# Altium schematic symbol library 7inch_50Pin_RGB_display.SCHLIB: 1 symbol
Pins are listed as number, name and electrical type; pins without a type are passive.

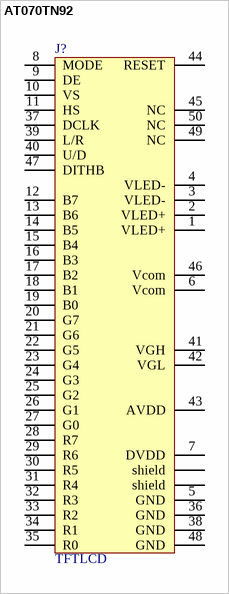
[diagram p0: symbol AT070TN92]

## AT070TN92
designator J?, comment TFTLCD
7' TFTLCD
footprint FPC-TOP50
pins: 1 VLED+, 2 VLED+, 3 VLED-, 4 VLED-, 5 GND, 6 Vcom, 7 DVDD, 8 MODE, 9 DE, 10 VS, 11 HS, 12 B7, 13 B6, 14 B5, 15 B4, 16 B3, 17 B2, 18 B1, 19 B0, 20 G7, 21 G6, 22 G5, 23 G4, 24 G3, 25 G2, 26 G1, 27 G0, 28 R7, 29 R6, 30 R5, 31 R4, 32 R3, 33 R2, 34 R1, 35 R0, 36 GND, 37 DCLK, 38 GND, 39 L/R, 40 U/D, 41 VGH, 42 VGL, 43 AVDD, 44 RESET, 45 NC, 46 Vcom, 47 DITHB, 48 GND, 49 NC, 50 NC, A shield, B shield
2 alternate drawings of the same symbol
